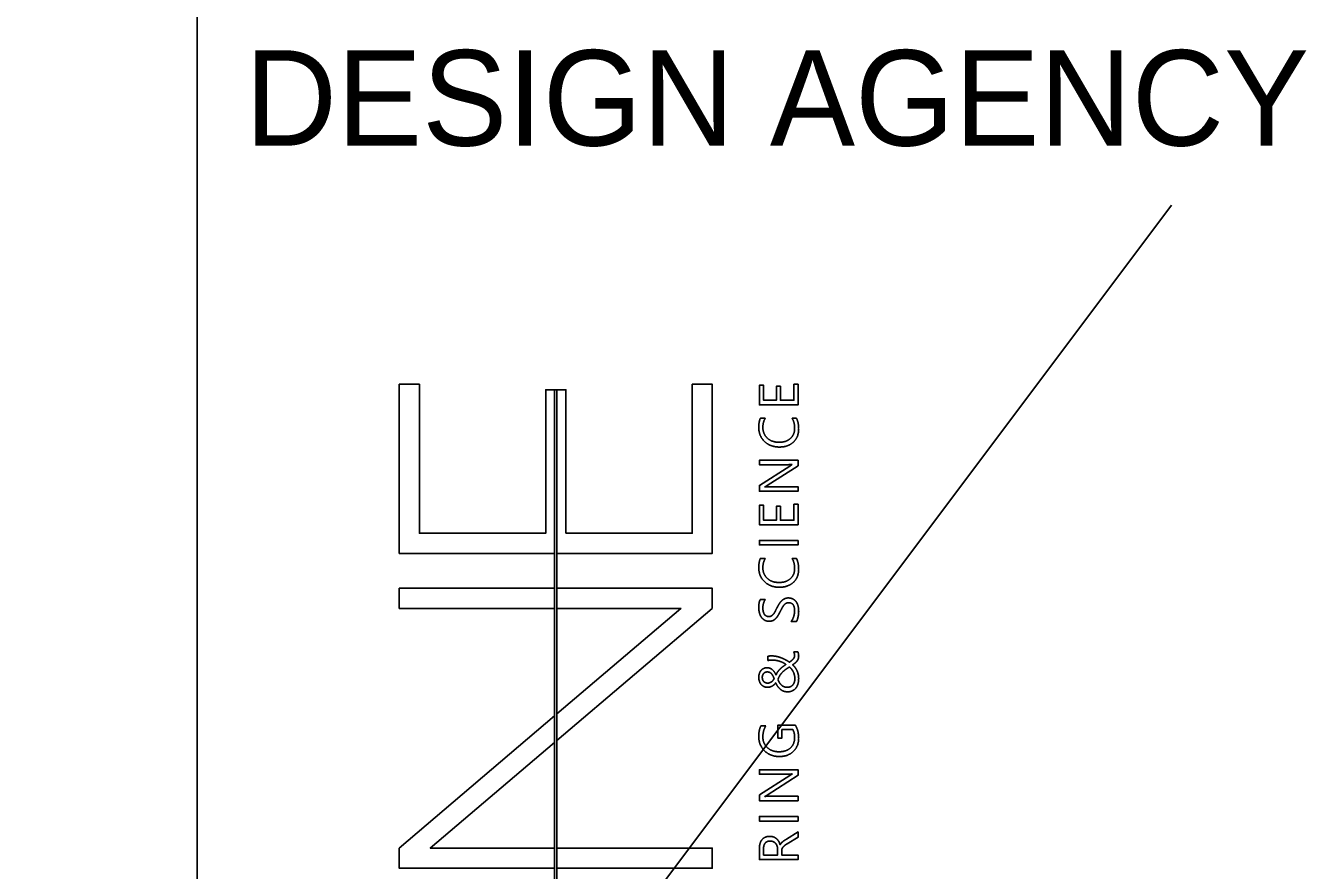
# Model space of a CAD drawing. Extents: x -17 to 34, y -2.3 to 22.
# Drawn here: x 31.821 to 33.162, y 3.591 to 4.476 of the extents above; entities that cross this region are included whole.
import ezdxf

# ---------------------------------------------------------------- set-up
doc = ezdxf.new("R2010")
doc.units = 0
for name, color, linetype in [('CS-ANNO', 7, 'Continuous'), ('CS-ANNO-MATC', 7, 'Continuous'), ('CS-PROF-TEXT', 7, 'Continuous')]:
    doc.layers.add(name, color=color, linetype=linetype)

msp = doc.modelspace()

# ---------------------------------------------------------------- linework, layer by layer
at = {"layer": 'CS-ANNO'}
msp.add_line((32, 0.5), (32, 21.5), dxfattribs=at)
at = {"layer": 'CS-ANNO-MATC'}
for p, q in [((32.2117, 4.1), (32.2328, 4.1)), ((32.2117, 3.9229), (32.2117, 4.1)), ((32.2328, 3.944), (32.2328, 4.1)), ((32.3651, 3.944), (32.3651, 4.0943)), ((32.3651, 4.0943), (32.3743, 4.0943)), ((32.3743, 4.0943), (32.3743, 3.4663)), ((32.3743, 4.0943), (32.3743, 3.9229)), ((32.3743, 4.0943), (32.3769, 4.0943)), ((32.3769, 4.0943), (32.3769, 3.4663)), ((32.3769, 4.0943), (32.3769, 3.9229)), ((32.3769, 4.0943), (32.3862, 4.0943)), ((32.3862, 3.944), (32.3862, 4.0943)), ((32.5185, 4.1), (32.5395, 4.1)), ((32.5185, 3.944), (32.5185, 4.1)), ((32.5395, 3.9229), (32.5395, 4.1)), ((32.5899, 4.0645), (32.595, 4.0645)), ((32.6231, 4.0645), (32.6277, 4.0645)), ((32.6233, 4.016), (32.6233, 4.0161)), ((32.5946, 3.9926), (32.5946, 3.9924)), ((32.2328, 3.944), (32.3651, 3.944)), ((32.3862, 3.944), (32.5185, 3.944)), ((32.2117, 3.9229), (32.3743, 3.9229)), ((32.3769, 3.9229), (32.5395, 3.9229)), ((32.5899, 3.9176), (32.595, 3.9176)), ((32.6231, 3.9176), (32.6277, 3.9176)), ((32.2117, 3.8652), (32.2117, 3.8863)), ((32.2117, 3.8863), (32.3743, 3.8863)), ((32.3743, 3.8863), (32.3743, 3.8652)), ((32.3769, 3.8863), (32.3769, 3.8652)), ((32.3769, 3.8863), (32.5395, 3.8863)), ((32.5395, 3.8652), (32.5395, 3.8863)), ((32.2117, 3.8652), (32.3743, 3.8652)), ((32.3769, 3.7547), (32.5067, 3.8652)), ((32.5395, 3.8652), (32.3769, 3.7269)), ((32.3769, 3.8652), (32.5067, 3.8652)), ((32.5897, 3.8745), (32.595, 3.8745)), ((32.6277, 3.8517), (32.6221, 3.8517)), ((32.5977, 3.8152), (32.5977, 3.8107)), ((32.6292, 3.8196), (32.6249, 3.8196)), ((32.63, 3.8153), (32.63, 3.8153)), ((32.5972, 3.7987), (32.5972, 3.7987)), ((32.626, 3.7917), (32.626, 3.7917)), ((32.2117, 3.6142), (32.3743, 3.7526)), ((32.3743, 3.7526), (32.3743, 3.7248)), ((32.3769, 3.7547), (32.3769, 3.7269)), ((32.5904, 3.7422), (32.5956, 3.7422)), ((32.3743, 3.7248), (32.2442, 3.6142)), ((32.6233, 3.6918), (32.6233, 3.6919)), ((32.5946, 3.6684), (32.5946, 3.6683)), ((32.2117, 3.5931), (32.2117, 3.6142)), ((32.2442, 3.6142), (32.3743, 3.6142)), ((32.3743, 3.6142), (32.3743, 3.5931)), ((32.3769, 3.6142), (32.3769, 3.5931)), ((32.3769, 3.6142), (32.5395, 3.6142)), ((32.5395, 3.5931), (32.5395, 3.6142)), ((32.6107, 3.6176), (32.6106, 3.6176)), ((32.2117, 3.5931), (32.3743, 3.5931)), ((32.3769, 3.5931), (32.5395, 3.5931))]:
    msp.add_line(p, q, dxfattribs=at)
for points in [[(32.2117, 4.1), (32.2117, 3.9229), (32.3743, 3.9229), (32.3743, 4.0943), (32.3651, 4.0943), (32.3651, 3.944), (32.2328, 3.944), (32.2328, 4.1)], [(32.3862, 3.944), (32.3862, 4.0943), (32.3769, 4.0943), (32.3769, 3.9229), (32.5395, 3.9229), (32.5395, 4.1), (32.5185, 4.1), (32.5185, 3.944)], [(32.6294, 4.1), (32.6294, 4.0785), (32.5889, 4.0785), (32.5889, 4.0991), (32.5932, 4.0991), (32.5932, 4.0833), (32.6067, 4.0833), (32.6067, 4.0979), (32.6109, 4.0979), (32.6109, 4.0833), (32.6251, 4.0833), (32.6251, 4.1)], [(32.6294, 3.9743), (32.6294, 3.9529), (32.5889, 3.9529), (32.5889, 3.9734), (32.5932, 3.9734), (32.5932, 3.9576), (32.6067, 3.9576), (32.6067, 3.9722), (32.6109, 3.9722), (32.6109, 3.9576), (32.6251, 3.9576), (32.6251, 3.9743)], [(32.6294, 3.9364), (32.6294, 3.9317), (32.5889, 3.9317), (32.5889, 3.9364)], [(32.2117, 3.8863), (32.2117, 3.8652), (32.3743, 3.8652), (32.3743, 3.8863)], [(32.3769, 3.8863), (32.3769, 3.8652), (32.5067, 3.8652), (32.3769, 3.7547), (32.3769, 3.7269), (32.5395, 3.8652), (32.5395, 3.8863)], [(32.2117, 3.6142), (32.2117, 3.5931), (32.3743, 3.5931), (32.3743, 3.6142), (32.2442, 3.6142), (32.3743, 3.7248), (32.3743, 3.7526)], [(32.6294, 3.6473), (32.6294, 3.6425), (32.5889, 3.6425), (32.5889, 3.6473)], [(32.3769, 3.6142), (32.3769, 3.5931), (32.5395, 3.5931), (32.5395, 3.6142)]]:
    msp.add_lwpolyline(points, close=True, dxfattribs=at)
for points in [[(32.4859, 3.4627), (32.3794, 3.4363), (32.3794, 3.4663), (32.3769, 3.4663), (32.3769, 4.0943), (32.3743, 4.0943), (32.3743, 3.4663), (32.3718, 3.4663), (32.3718, 3.4344), (32.3124, 3.4197)], [(32.6174, 4.0158), (32.5889, 4.0158), (32.5889, 4.0205), (32.6294, 4.0205), (32.6294, 4.0147), (32.5971, 3.9939)], [(32.6001, 3.9927), (32.6294, 3.9927), (32.6294, 3.9879), (32.5889, 3.9879), (32.5889, 3.9941), (32.6206, 4.0143)], [(32.6239, 3.7383), (32.6125, 3.7383), (32.6125, 3.7294), (32.6083, 3.7294), (32.6083, 3.743), (32.6266, 3.743)], [(32.6174, 3.6916), (32.5889, 3.6916), (32.5889, 3.6963), (32.6294, 3.6963), (32.6294, 3.6905), (32.5971, 3.6697)], [(32.6001, 3.6685), (32.6294, 3.6685), (32.6294, 3.6638), (32.5889, 3.6638), (32.5889, 3.6699), (32.6206, 3.6901)], [(32.618, 3.6187), (32.6294, 3.6255), (32.6294, 3.6311), (32.6172, 3.6236)], [(32.5889, 3.6142), (32.5889, 3.6022), (32.6294, 3.6022), (32.6294, 3.6069), (32.6122, 3.6069), (32.6122, 3.6108)], [(32.6079, 3.6133), (32.6079, 3.6069), (32.5932, 3.6069), (32.5932, 3.6134)]]:
    msp.add_lwpolyline(points, dxfattribs=at)
for points in [[(32.5882, 4.055), (32.5882, 4.0607), (32.5899, 4.0645)], [(32.595, 4.0645), (32.5925, 4.0601), (32.5925, 4.0549)], [(32.6258, 4.0539), (32.6258, 4.06), (32.6231, 4.0645)], [(32.6277, 4.0645), (32.63, 4.06), (32.63, 4.0533)], [(32.5942, 4.0402), (32.5882, 4.046), (32.5882, 4.055)], [(32.5925, 4.0549), (32.5925, 4.0479), (32.5972, 4.0436)], [(32.6214, 4.0433), (32.6258, 4.0474), (32.6258, 4.0539)], [(32.63, 4.0533), (32.63, 4.0447), (32.6245, 4.0395)], [(32.6099, 4.0343), (32.6002, 4.0343), (32.5942, 4.0402)], [(32.5972, 4.0436), (32.6018, 4.0393), (32.6096, 4.0393)], [(32.6096, 4.0393), (32.617, 4.0393), (32.6214, 4.0433)], [(32.6245, 4.0395), (32.6189, 4.0343), (32.6099, 4.0343)], [(32.6233, 4.0161), (32.6216, 4.0158), (32.6174, 4.0158)], [(32.6206, 4.0143), (32.6226, 4.0156), (32.6233, 4.016)], [(32.5971, 3.9939), (32.5959, 3.9931), (32.5946, 3.9926)], [(32.5946, 3.9924), (32.5959, 3.9927), (32.6001, 3.9927)], [(32.5882, 3.9081), (32.5882, 3.9138), (32.5899, 3.9176)], [(32.595, 3.9176), (32.5925, 3.9133), (32.5925, 3.908)], [(32.6258, 3.9071), (32.6258, 3.9132), (32.6231, 3.9176)], [(32.6277, 3.9176), (32.63, 3.9131), (32.63, 3.9064)], [(32.5942, 3.8933), (32.5882, 3.8991), (32.5882, 3.9081)], [(32.5925, 3.908), (32.5925, 3.9011), (32.5972, 3.8967)], [(32.6214, 3.8965), (32.6258, 3.9005), (32.6258, 3.9071)], [(32.63, 3.9064), (32.63, 3.8978), (32.6245, 3.8926)], [(32.6099, 3.8874), (32.6002, 3.8874), (32.5942, 3.8933)], [(32.5972, 3.8967), (32.6018, 3.8924), (32.6096, 3.8924)], [(32.6096, 3.8924), (32.617, 3.8924), (32.6214, 3.8965)], [(32.6245, 3.8926), (32.6189, 3.8874), (32.6099, 3.8874)], [(32.6151, 3.8753), (32.6169, 3.8762), (32.6191, 3.8762)], [(32.6191, 3.8762), (32.6221, 3.8762), (32.6242, 3.875)], [(32.5882, 3.8658), (32.5882, 3.8718), (32.5897, 3.8745)], [(32.5889, 3.8606), (32.5882, 3.8632), (32.5882, 3.8658)], [(32.595, 3.8745), (32.5925, 3.8709), (32.5925, 3.8653)], [(32.5925, 3.8653), (32.5925, 3.8638), (32.5929, 3.8622)], [(32.6052, 3.8617), (32.606, 3.8634), (32.6071, 3.8655)], [(32.6071, 3.8655), (32.6082, 3.8677), (32.6093, 3.8696)], [(32.6093, 3.8696), (32.6105, 3.8715), (32.612, 3.873)], [(32.6125, 3.8655), (32.6116, 3.8638), (32.6106, 3.8618)], [(32.612, 3.873), (32.6134, 3.8745), (32.6151, 3.8753)], [(32.6144, 3.8685), (32.6134, 3.8673), (32.6125, 3.8655)], [(32.6166, 3.8705), (32.6154, 3.8698), (32.6144, 3.8685)], [(32.6195, 3.8712), (32.6178, 3.8712), (32.6166, 3.8705)], [(32.6242, 3.8691), (32.6225, 3.8712), (32.6195, 3.8712)], [(32.6242, 3.875), (32.6263, 3.8739), (32.6276, 3.8719)], [(32.6258, 3.8625), (32.6258, 3.8669), (32.6242, 3.8691)], [(32.6255, 3.8598), (32.6258, 3.8613), (32.6258, 3.8625)], [(32.6276, 3.8719), (32.6289, 3.8699), (32.6295, 3.8673)], [(32.6295, 3.8673), (32.63, 3.8647), (32.63, 3.8618)], [(32.5909, 3.8561), (32.5895, 3.8581), (32.5889, 3.8606)], [(32.5942, 3.853), (32.5922, 3.8542), (32.5909, 3.8561)], [(32.5929, 3.8622), (32.5932, 3.8607), (32.5939, 3.8594)], [(32.5939, 3.8594), (32.5946, 3.8582), (32.5958, 3.8575)], [(32.599, 3.8518), (32.5963, 3.8518), (32.5942, 3.853)], [(32.5958, 3.8575), (32.597, 3.8567), (32.5986, 3.8567)], [(32.5986, 3.8567), (32.6002, 3.8567), (32.6013, 3.8573)], [(32.603, 3.8525), (32.6013, 3.8518), (32.599, 3.8518)], [(32.6013, 3.8573), (32.6024, 3.8579), (32.6034, 3.859)], [(32.606, 3.8547), (32.6047, 3.8533), (32.603, 3.8525)], [(32.6034, 3.859), (32.6043, 3.8601), (32.6052, 3.8617)], [(32.6084, 3.8578), (32.6073, 3.856), (32.606, 3.8547)], [(32.6106, 3.8618), (32.6095, 3.8597), (32.6084, 3.8578)], [(32.6221, 3.8517), (32.623, 3.8527), (32.6237, 3.854)], [(32.6237, 3.854), (32.6243, 3.8553), (32.6248, 3.8568)], [(32.6248, 3.8568), (32.6253, 3.8583), (32.6255, 3.8598)], [(32.6287, 3.8538), (32.6283, 3.8525), (32.6277, 3.8517)], [(32.6294, 3.8566), (32.6291, 3.8551), (32.6287, 3.8538)], [(32.6299, 3.8594), (32.6297, 3.858), (32.6294, 3.8566)], [(32.63, 3.8618), (32.63, 3.8609), (32.6299, 3.8594)], [(32.5995, 3.8154), (32.5987, 3.8154), (32.5977, 3.8152)], [(32.5977, 3.8107), (32.5987, 3.8109), (32.5996, 3.811)], [(32.6015, 3.8155), (32.6003, 3.8155), (32.5995, 3.8154)], [(32.5996, 3.811), (32.6006, 3.8112), (32.6016, 3.8112)], [(32.6067, 3.815), (32.6041, 3.8155), (32.6015, 3.8155)], [(32.6016, 3.8112), (32.6058, 3.8112), (32.6097, 3.81)], [(32.6117, 3.8135), (32.6092, 3.8145), (32.6067, 3.815)], [(32.6097, 3.81), (32.6135, 3.8088), (32.6167, 3.8066)], [(32.6163, 3.8114), (32.6141, 3.8126), (32.6117, 3.8135)], [(32.6204, 3.8089), (32.6185, 3.8102), (32.6163, 3.8114)], [(32.6227, 3.8107), (32.6217, 3.8099), (32.6204, 3.8089)], [(32.6244, 3.8124), (32.6237, 3.8115), (32.6227, 3.8107)], [(32.6254, 3.8141), (32.6251, 3.8132), (32.6244, 3.8124)], [(32.6249, 3.8196), (32.6253, 3.8187), (32.6255, 3.8178)], [(32.6257, 3.8161), (32.6257, 3.815), (32.6254, 3.8141)], [(32.6255, 3.8178), (32.6257, 3.817), (32.6257, 3.8161)], [(32.6264, 3.8082), (32.6275, 3.8092), (32.6283, 3.8102)], [(32.6283, 3.8102), (32.6291, 3.8113), (32.6296, 3.8125)], [(32.6298, 3.8175), (32.6296, 3.8186), (32.6292, 3.8196)], [(32.6296, 3.8125), (32.63, 3.8137), (32.63, 3.8153)], [(32.63, 3.8153), (32.63, 3.8164), (32.6298, 3.8175)], [(32.5889, 3.7972), (32.5882, 3.7953), (32.5882, 3.7931)], [(32.5906, 3.8003), (32.5895, 3.799), (32.5889, 3.7972)], [(32.5933, 3.8023), (32.5917, 3.8016), (32.5906, 3.8003)], [(32.5922, 3.7951), (32.5925, 3.7961), (32.5932, 3.7969)], [(32.5932, 3.7969), (32.5938, 3.7977), (32.5948, 3.7982)], [(32.5968, 3.8031), (32.5949, 3.8031), (32.5933, 3.8023)], [(32.5948, 3.7982), (32.5958, 3.7987), (32.5972, 3.7987)], [(32.6024, 3.8011), (32.6002, 3.8031), (32.5968, 3.8031)], [(32.5972, 3.7987), (32.5997, 3.7987), (32.6014, 3.797)], [(32.6014, 3.797), (32.603, 3.7952), (32.6043, 3.7917)], [(32.6063, 3.7953), (32.6047, 3.7992), (32.6024, 3.8011)], [(32.6081, 3.7989), (32.607, 3.7973), (32.6063, 3.7953)], [(32.6106, 3.8018), (32.6092, 3.8004), (32.6081, 3.7989)], [(32.6101, 3.7947), (32.6111, 3.7964), (32.6125, 3.7979)], [(32.6135, 3.8043), (32.6119, 3.8031), (32.6106, 3.8018)], [(32.6125, 3.7979), (32.6138, 3.7993), (32.6157, 3.8008)], [(32.6167, 3.8066), (32.615, 3.8054), (32.6135, 3.8043)], [(32.6157, 3.8008), (32.6177, 3.8022), (32.6203, 3.804)], [(32.6203, 3.804), (32.6215, 3.8029), (32.6225, 3.8017)], [(32.6225, 3.8017), (32.6235, 3.8005), (32.6243, 3.7989)], [(32.6237, 3.8062), (32.6252, 3.8072), (32.6264, 3.8082)], [(32.6261, 3.8036), (32.625, 3.805), (32.6237, 3.8062)], [(32.6243, 3.7989), (32.6251, 3.7974), (32.6255, 3.7956)], [(32.6255, 3.7956), (32.626, 3.7938), (32.626, 3.7917)], [(32.6281, 3.8003), (32.6272, 3.8021), (32.6261, 3.8036)], [(32.6295, 3.7963), (32.629, 3.7985), (32.6281, 3.8003)], [(32.63, 3.7917), (32.63, 3.7942), (32.6295, 3.7963)], [(32.5882, 3.7931), (32.5882, 3.7909), (32.5889, 3.789)], [(32.5889, 3.789), (32.5895, 3.7871), (32.5906, 3.7857)], [(32.5906, 3.7857), (32.5918, 3.7843), (32.5935, 3.7835)], [(32.5919, 3.7931), (32.5919, 3.7941), (32.5922, 3.7951)], [(32.5934, 3.7887), (32.5919, 3.7904), (32.5919, 3.7931)], [(32.5975, 3.787), (32.5949, 3.7871), (32.5934, 3.7887)], [(32.5935, 3.7835), (32.5953, 3.7826), (32.5975, 3.7826)], [(32.5997, 3.7874), (32.5986, 3.787), (32.5975, 3.787)], [(32.5975, 3.7826), (32.599, 3.7826), (32.6003, 3.7831)], [(32.6016, 3.7884), (32.6007, 3.7878), (32.5997, 3.7874)], [(32.6003, 3.7831), (32.6016, 3.7835), (32.6026, 3.7841)], [(32.6031, 3.7899), (32.6024, 3.789), (32.6016, 3.7884)], [(32.6026, 3.7841), (32.6037, 3.7848), (32.6045, 3.7856)], [(32.6043, 3.7917), (32.6038, 3.7907), (32.6031, 3.7899)], [(32.6045, 3.7856), (32.6054, 3.7865), (32.606, 3.7873)], [(32.606, 3.7873), (32.6079, 3.7828), (32.611, 3.7804)], [(32.6083, 3.7908), (32.6091, 3.793), (32.6101, 3.7947)], [(32.6098, 3.7876), (32.609, 3.789), (32.6083, 3.7908)], [(32.6119, 3.785), (32.6107, 3.7861), (32.6098, 3.7876)], [(32.6146, 3.7833), (32.613, 3.7839), (32.6119, 3.785)], [(32.6182, 3.7826), (32.6161, 3.7826), (32.6146, 3.7833)], [(32.6216, 3.7834), (32.6201, 3.7826), (32.6182, 3.7826)], [(32.624, 3.7853), (32.6231, 3.7841), (32.6216, 3.7834)], [(32.6255, 3.7881), (32.625, 3.7865), (32.624, 3.7853)], [(32.626, 3.7917), (32.626, 3.7898), (32.6255, 3.7881)], [(32.627, 3.7817), (32.6285, 3.7836), (32.6292, 3.7861)], [(32.6292, 3.7861), (32.63, 3.7886), (32.63, 3.7917)], [(32.611, 3.7804), (32.614, 3.7779), (32.6184, 3.7779)], [(32.6184, 3.7779), (32.6212, 3.7779), (32.6233, 3.7789)], [(32.6233, 3.7789), (32.6255, 3.7799), (32.627, 3.7817)], [(32.5882, 3.7311), (32.5882, 3.7377), (32.5904, 3.7422)], [(32.5956, 3.7422), (32.5925, 3.7373), (32.5925, 3.7306)], [(32.6266, 3.743), (32.63, 3.7369), (32.63, 3.7295)], [(32.5943, 3.7161), (32.5882, 3.722), (32.5882, 3.7311)], [(32.5925, 3.7306), (32.5925, 3.7238), (32.5972, 3.7194)], [(32.6214, 3.7191), (32.6258, 3.7232), (32.6258, 3.7301)], [(32.6258, 3.7301), (32.6258, 3.7348), (32.6239, 3.7383)], [(32.63, 3.7295), (32.63, 3.7208), (32.6244, 3.7155)], [(32.6097, 3.7101), (32.6003, 3.7101), (32.5943, 3.7161)], [(32.5972, 3.7194), (32.6019, 3.7151), (32.6093, 3.7151)], [(32.6093, 3.7151), (32.617, 3.7151), (32.6214, 3.7191)], [(32.6244, 3.7155), (32.6189, 3.7101), (32.6097, 3.7101)], [(32.6233, 3.6919), (32.6216, 3.6916), (32.6174, 3.6916)], [(32.6206, 3.6901), (32.6226, 3.6914), (32.6233, 3.6918)], [(32.5971, 3.6697), (32.5959, 3.6689), (32.5946, 3.6684)], [(32.5946, 3.6683), (32.5959, 3.6685), (32.6001, 3.6685)], [(32.5916, 3.623), (32.5902, 3.6214), (32.5896, 3.6191)], [(32.595, 3.6256), (32.593, 3.6247), (32.5916, 3.623)], [(32.5997, 3.6265), (32.597, 3.6265), (32.595, 3.6256)], [(32.595, 3.6195), (32.5968, 3.6216), (32.6001, 3.6216)], [(32.6036, 3.6259), (32.6018, 3.6265), (32.5997, 3.6265)], [(32.6001, 3.6216), (32.6019, 3.6216), (32.6033, 3.6209)], [(32.6067, 3.6241), (32.6053, 3.6253), (32.6036, 3.6259)], [(32.6091, 3.6213), (32.6081, 3.6229), (32.6067, 3.6241)], [(32.6106, 3.6176), (32.61, 3.6196), (32.6091, 3.6213)], [(32.6149, 3.6221), (32.6139, 3.6214), (32.6131, 3.6207)], [(32.6172, 3.6236), (32.6159, 3.6227), (32.6149, 3.6221)], [(32.5896, 3.6191), (32.5889, 3.6169), (32.5889, 3.6142)], [(32.5932, 3.6134), (32.5932, 3.6174), (32.595, 3.6195)], [(32.6033, 3.6209), (32.6048, 3.6203), (32.6058, 3.6192)], [(32.6058, 3.6192), (32.6068, 3.6181), (32.6073, 3.6166)], [(32.6073, 3.6166), (32.6079, 3.6151), (32.6079, 3.6133)], [(32.6117, 3.6193), (32.6111, 3.6186), (32.6107, 3.6176)], [(32.6131, 3.6207), (32.6123, 3.6201), (32.6117, 3.6193)], [(32.6122, 3.6108), (32.6122, 3.6121), (32.6125, 3.6132)], [(32.6125, 3.6132), (32.6128, 3.6142), (32.6135, 3.6151)], [(32.6135, 3.6151), (32.6142, 3.6161), (32.6153, 3.6169)], [(32.6153, 3.6169), (32.6164, 3.6178), (32.618, 3.6187)]]:
    msp.add_open_spline(points, degree=2, dxfattribs=at)
at = {"layer": 'CS-PROF-TEXT'}
msp.add_line((31.8205, 2.6878), (33.0205, 4.2878), dxfattribs=at)

# ---------------------------------------------------------------- texts
at = {"layer": 'CS-ANNO-MATC'}
msp.add_text('DESIGN AGENCY', height=0.1, dxfattribs=at).set_placement((32.05, 4.35))

doc.saveas('drawing.dxf')
